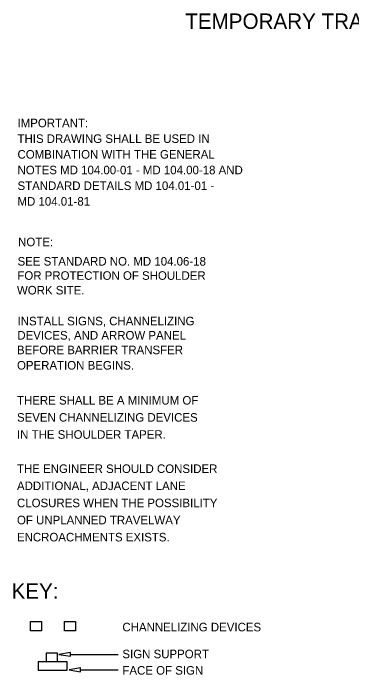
# Model space of a CAD drawing. Extents: x 54531.5 to 54538.4, y 53883.4 to 53893.4.
# Drawn here: x 54531.484 to 54533.856, y 53888.808 to 53893.449 of the extents above; entities that cross this region are included whole.
import ezdxf

# ---------------------------------------------------------------- set-up
doc = ezdxf.new("R2010")
doc.units = 0
for name, color, linetype in [('DETL-DIMS', 7, 'Continuous'), ('DETL-LINE', 7, 'Continuous'), ('DETL-NOTE', 7, 'Continuous'), ('DETL-TITL', 7, 'Continuous'), ('USER-BORD', 7, 'Continuous')]:
    doc.layers.add(name, color=color, linetype=linetype)

# ---------------------------------------------------------------- blocks, each defined once
blk = doc.blocks.new('SIGN13')
at = {"layer": 'USER-BORD'}
for points in [[(-0.134, 0.182), (0.11, 0.189), (0.11, 0.371), (-0.134, 0.371)], [(-0.314, 0.182), (-0.314, 0), (0.32, 0), (0.32, 0.182)]]:
    blk.add_lwpolyline(points, close=True, dxfattribs=at)

msp = doc.modelspace()

# ---------------------------------------------------------------- linework, layer by layer
at = {"layer": 'DETL-DIMS'}
for p, q in [((54531.8842, 53888.9514), (54532.2195, 53888.9514)), ((54531.9558, 53888.843), (54532.2195, 53888.843))]:
    msp.add_line(p, q, dxfattribs=at)
for points in [[(54531.8842, 53888.938), (54531.8842, 53888.9647), (54531.8042, 53888.9514)], [(54531.9558, 53888.8296), (54531.9558, 53888.8563), (54531.8758, 53888.843)]]:
    msp.add_lwpolyline(points, close=True, dxfattribs=at)
at = {"layer": 'DETL-LINE'}
for points in [[(54531.605, 53889.1176), (54531.605, 53889.1822), (54531.6817, 53889.1822), (54531.6817, 53889.1176)], [(54531.8438, 53889.1176), (54531.8438, 53889.1822), (54531.9204, 53889.1822), (54531.9204, 53889.1176)]]:
    msp.add_lwpolyline(points, close=True, dxfattribs=at)

# ---------------------------------------------------------------- block references
at = {"layer": 'DETL-LINE', "xscale": 0.32, "yscale": 0.32}
msp.add_blockref('SIGN13', (54531.7583, 53888.8399), dxfattribs=at)

# ---------------------------------------------------------------- texts
at = {"layer": 'DETL-NOTE'}
for s, p in [('IMPORTANT:', (54531.5136, 53892.6489)), ('THIS DRAWING SHALL BE USED IN', (54531.5136, 53892.5389)), ('COMBINATION WITH THE GENERAL', (54531.5136, 53892.4289)), ('NOTES MD 104.00-01 - MD 104.00-18 AND', (54531.5136, 53892.3189)), ('STANDARD DETAILS MD 104.01-01 -', (54531.5136, 53892.2089)), ('MD 104.01-81', (54531.5136, 53892.0989)), ('NOTE:', (54531.5178, 53891.8144)), ('SEE STANDARD NO. MD 104.06-18', (54531.5139, 53891.6784)), ('FOR PROTECTION OF SHOULDER', (54531.5125, 53891.5788)), ('WORK SITE.', (54531.5099, 53891.476)), ('INSTALL SIGNS, CHANNELIZING', (54531.5139, 53891.2593)), ('DEVICES, AND ARROW PANEL', (54531.5125, 53891.1597)), ('BEFORE BARRIER TRANSFER', (54531.5099, 53891.0568)), ('OPERATION BEGINS.', (54531.5099, 53890.9492)), ('THERE SHALL BE A MINIMUM OF ', (54531.5099, 53890.7037)), ('SEVEN CHANNELIZING DEVICES ', (54531.5099, 53890.5837)), ('IN THE SHOULDER TAPER.', (54531.5099, 53890.4637)), ('THE ENGINEER SHOULD CONSIDER', (54531.5099, 53890.2237)), ('ADDITIONAL, ADJACENT LANE', (54531.5099, 53890.1037)), ('CLOSURES WHEN THE POSSIBILITY', (54531.5099, 53889.9837)), ('OF UNPLANNED TRAVELWAY', (54531.5099, 53889.8637)), ('ENCROACHMENTS EXISTS.', (54531.5099, 53889.7437)), ('CHANNELIZING DEVICES', (54532.2486, 53889.1127)), ('SIGN SUPPORT', (54532.2486, 53888.9241)), ('FACE OF SIGN', (54532.2486, 53888.8091))]:
    msp.add_text(s, height=0.06, dxfattribs=at).set_placement(p)
at = {"layer": 'DETL-TITL'}
for s, p in [('TEMPORARY TRAFFIC CONTROL TYPICAL APPLICATION', (54532.6891, 53893.3391)), ('KEY:', (54531.4719, 53889.3417))]:
    msp.add_text(s, height=0.108, dxfattribs=at).set_placement(p)

doc.saveas('drawing.dxf')
